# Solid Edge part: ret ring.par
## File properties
Author: Deepak Maini
Template: normal.par
Last saved by: Robert a Rhodes jr
Revision: 3
Application: Solid Edge
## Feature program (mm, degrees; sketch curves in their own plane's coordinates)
sketch for "unnamed RevolvedProtrusion 1" plane through (0, 25.4, 0) normal (0, -1, 0) x-axis (1, 0, 0)
  line (-42.2288, 1.129) -> (-38.3369, 1.129)
  line (-38.3369, 1.129) -> (-38.3369, 0)
  line (-38.3369, 0) -> (-42.2288, 0)
  line (-42.2288, 0) -> (-42.2288, 1.129)
revolve "unnamed RevolvedProtrusion 1" add finite about sketch line (-42.1776, -8.3958) -> (-20.1067, -8.3958)
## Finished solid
Body 1: solid body, 6 faces, 12 edges, 8 vertices.
  Faces by surface: plane 4, cylinder 2
  Edges by curve: line 8, circle 4
Bounding box of the edges (mm): 3.892 x 19.050 x 18.157, from (-42.2288, 15.8752, -17.0282) to (-38.3369, 34.9248, 1.129).
Cylindrical faces by radius (mm): R8.3958 x1, R9.5248 x1
Planar faces by outward normal: +x 1, -x 1, oblique 2
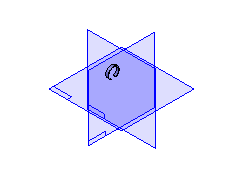
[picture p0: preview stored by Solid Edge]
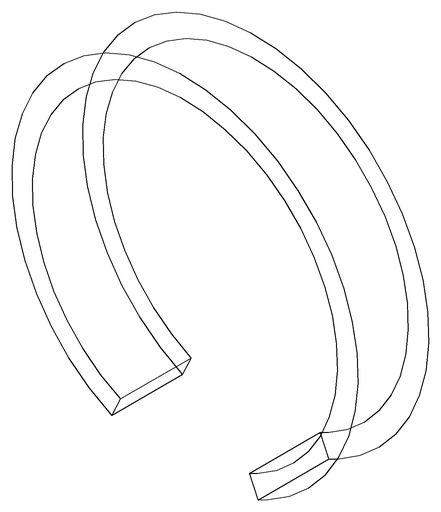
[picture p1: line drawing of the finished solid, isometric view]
